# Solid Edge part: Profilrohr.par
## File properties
Username: bmolnar
Dokumentum tartalom típus: 0
Author: bmolnar
Last saved by: bmolnar
Revision: 81
Sűrűség: 0,000 kg/m^3
Pontosság: 0,990
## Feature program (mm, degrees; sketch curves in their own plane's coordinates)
base feature "unnamed BaseFeature 1"
thread "unnamed Thread 1"
thread "Menet_2"  ThreadDepth = 7.5 mm
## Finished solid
Body 1: solid body, 157 faces, 384 edges, 250 vertices.
  Faces by surface: plane 102, cylinder 41, cone 10, torus 4
  Edges by curve: line 284, circle 92, curve on surface 7, intersection 1
Bounding box of the edges (mm; curved faces can reach further): 80.000 x 86.000 x 67.000, from (-40, -40, 0) to (40, 46, 67).
Cylindrical faces by radius (mm): R1.6 x2, R4.283 x4, R4.55 x7, R4.555 x1, R7 x16, R31.5 x1, R32.35 x2, R32.55 x2, R34.1 x2, R53 x4
Conical faces (half-angle, radius in mm at the cone's reference point): 30 deg R31.825 x2, 30 deg R32.6387 x2, 45 deg R4.533 x2, 45 deg R32.7 x2, 45 deg R32.8 x2
Toroidal faces (ring radius, tube radius in mm): R33.9 r0.2 x4
Planar faces by outward normal: +x 9, +y 11, +z 8, -x 9, -y 9, -z 8, oblique 48
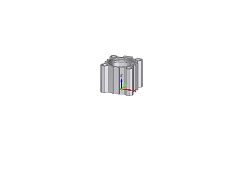
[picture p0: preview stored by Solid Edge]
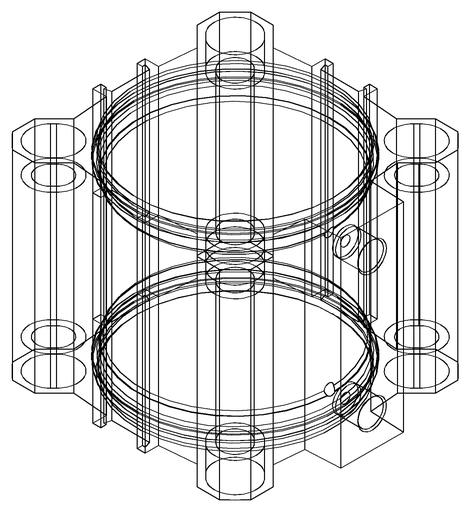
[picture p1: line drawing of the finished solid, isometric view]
